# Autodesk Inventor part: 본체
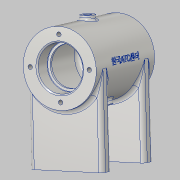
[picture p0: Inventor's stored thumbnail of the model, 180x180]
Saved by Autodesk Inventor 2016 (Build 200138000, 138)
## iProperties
Created: 2020-07
Part Number: 본체
Material: 알루미늄 6061
Document SubType Name: Modeling
Designer: 605-17
Density: 2.7 g/cm^3
Appearance: 알루미늄 - 평지
Mass: 305.265 g
Surface Area: 357.573 cm^2
Volume: 113.061 cm^3
Author: 605-17
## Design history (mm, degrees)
sketch "스케치1"
  geometry: C1 r 26 at (0, 0); 1 further point
  constraints: 1 centre point, 1 coincident
  dimensions: "d0" = 52 diameter of C1
extrude "돌출1" new body sketch "스케치1" stored distance "d1" = 70; taper "d2" = 0 deg
sketch "스케치2"
  geometry: L1 (26, -35)-(-26, -35) reference; L2 (-26, -35)-(-26, 35) reference; L3 (-26, 35)-(26, 35) reference; L4 (26, 35)-(26, -35) reference; L5 (26, 35)-(-26, 35) reference; L6 (0, 35)-(0, -35); L7 (16, 35)-(16, 23); L8 (16, 23)-(14, 23); L9 (14, 23)-(14, 21); L10 (14, 21)-(21, 21); L11 (21, 21)-(21, -21); L12 (21, -21)-(14, -21); L13 (14, -21)-(14, -23); L14 (14, -23)-(16, -23); L15 (16, -23)-(16, -35); 1 further point
  constraints: 20 end point, 9 perpendicular, 2 midpoint, 2 point on line
  dimensions: "d3" = 32 diameter of L7 L6; "d4" = 28 diameter of L9 L6; "d5" = 42 diameter of L11 L6; "d6" = 28 diameter of L13 L6; "d7" = 32 diameter of L15 L6; "d8" = 12 distance of L7.start L7.end; "d9" = 2 distance of L8.end L9.end; "d10" = 42 distance of L10.end L11.end; "d11" = 12 distance of L14.end L15.end
revolve "회전1" sketch "스케치2" stored, may be unused: angle "d12" = 90 deg
node "작업 평면2"
sketch "스케치3"
  geometry: L1 (0, 0)-(-26, 0); L2 (0, 0)-(26, 0); L3 (-26, 0)-(-26, -64); L4 (26, 0)-(26, -64); L5 (-26, -64)-(26, -64); C1 r 21 at (0, 0) reference; A1 r 26 centre (0, 0) between (-26, 0) and (26, 0) reference; 1 further point
  constraints: 10 end point, 2 horizontal, 2 point on circle, 2 vertical
  dimensions: "d15" = 64 distance of L1.end L3.end; "d16" = 64 distance of L2.end L4.end
extrude "돌출2" join sketch "스케치3" distance "d17" = 10; taper "d18" = 0 deg
sketch "스케치4" dims "d19" = 42
  geometry: L1 (0, 0)-(0, 21); C1 r 16 at (0, 0) reference; C2 r 26 at (0, 0) reference; 1 further point
  constraints: 2 end point, 1 coincident, 1 vertical, 1 vertical alignment, 2 other
hole "구멍1" sketch "스케치4" at (0, 21) diameter "d20" = 3.242; stored, may be unused: countersink angle "d24" = 90 deg, drill point angle "d26" = 118 deg; dims "d21" = 8, "d22" = 4, "d23" = 2, "d25" = 10
node "작업 평면3"
sketch "스케치5"
  geometry: C1 r 5 at (0, 0); 1 further point
  constraints: 1 centre point, 1 coincident
  dimensions: "d31" = 10 diameter of C1
extrude "돌출3" join sketch "스케치5" stored distance "d32" = 10; taper "d33" = 0 deg
hole "구멍2" diameter "d36" = 5.188; stored, may be unused: countersink angle "d40" = 90 deg, drill point angle "d42" = 118 deg; dims "d34" = 10, "d35" = 10, "d37" = 12, "d38" = 4, "d39" = 2, "d41" = 18
sketch "스케치6"
  geometry: L1 (0, 0)-(0, -26); L2 (0, 0)-(9.919, -27.251); C1 r 14 at (0, 0) reference; 1 further point
  constraints: 4 end point, 1 vertical, 1 vertical alignment, 1 other
  dimensions: "d43" = 29 distance of L1.start L2.end; "d44" = 20 deg angle of L2 L1
node "작업 평면4"
sketch "스케치7"
  geometry: C1 r 6 at (0, 0); 1 further point
  constraints: 1 centre point, 1 coincident
  dimensions: "d45" = 12 diameter of C1
extrude "돌출4" join sketch "스케치7" stored distance "d46" = 10; taper "d47" = 0 deg
hole "구멍3" diameter "d50" = 5.188; stored, may be unused: countersink angle "d54" = 90 deg, drill point angle "d56" = 118 deg; dims "d48" = 10, "d49" = 10, "d51" = 12, "d52" = 4, "d53" = 2, "d55" = 18
fillet "모깎기1" dims "d57" = 0.3
fillet "모깎기2" dims "d58" = 0.3
fillet "모깎기3" dims "d59" = 3
chamfer "모따기1" distance "d60" = 1; stored, may be unused: second distance "d61" = 2, angle "d62" = 45 deg
fillet "모깎기4" dims "d63" = 2
fillet "모깎기5" dims "d64" = 2
fillet "모깎기6" dims "d65" = 3
fillet "모깎기7" dims "d66" = 3
sketch "스케치8"
  geometry: L1 (0, 10)-(46, 10) reference; L2 (0, 0)-(46, 0) reference; L3 (0, -40)-(46, -40) reference; L4 (0, -50)-(46, -50) reference; L5 (49, 3)-(49, 7) reference; L6 (49, 5)-(-3, 5); L7 (-3, 3)-(-3, 7) reference; L8 (49, -43)-(49, -47) reference; L9 (49, -45)-(-3, -45); L10 (-3, -43)-(-3, -47) reference; L11 (23, -20)-(23, 15.057); L12 (49, -55)-(49, 15) reference; L13 (-3, -55)-(-3, 15) reference; L14 (23, -20)-(23, -55); L15 (43, 17.445)-(43, -57.156); L16 (3, 20.788)-(3, -59.066); L17 (45.621, 5)-(42.379, 5) reference; L18 (3.621, 5)-(0.379, 5) reference; L19 (45.621, -45)-(42.379, -45) reference; C1 r 2.594 at (23, -20) reference; 4 further points
  constraints: 12 end point, 8 point on line, 4 midpoint, 4 vertical
  dimensions: "d67" = 20 distance between parallel lines of L11 L15; "d68" = 20 distance between parallel lines of L16 L11
hole "구멍4" sketch "스케치8" at (43, 5), (3, 5), (43, -45), (3, -45) diameter "d69" = 4.134; stored, may be unused: countersink angle "d73" = 90 deg, drill point angle "d75" = 118 deg; dims "d70" = 8, "d71" = 4, "d72" = 2, "d74" = 10
sketch "스케치9"
  geometry: L1 (29, 5)-(29, -5) reference; L2 (17, 35)-(-17, 35) reference; 2 further points
  constraints: 1 other
  dimensions: "d76" = 26 distance from line of L1 point (3, 0); "d77" = 35 distance from line of L2 point (3, 0)
feature "엠보싱1" sketch "스케치9" dims "d78" = 0.5, "d79" = 0
node "솔리드1"
mirror "대칭1"
pattern_circular "원형 패턴1" dims angle "d28" = 360 deg
mirror "대칭2"
node "투영된 루프1"
node "절단 모서리 투영1"
node "절단 모서리 투영2"
other parameters: "d30" = 29
